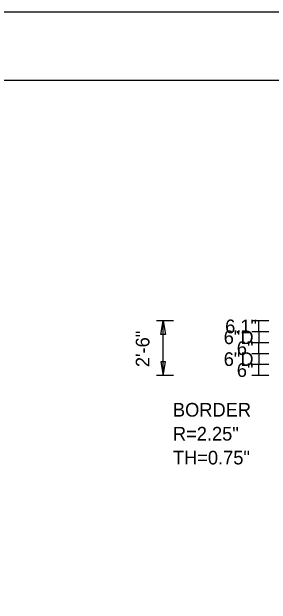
# Model space of a CAD drawing. Extents: x 1806251 to 1809821, y 414895 to 422886.
# Drawn here: x 1809675.736 to 1809677.16, y 415070.976 to 415074.226 of the extents above; entities that cross this region are included whole.
import ezdxf

# ---------------------------------------------------------------- set-up
doc = ezdxf.new("R2010")
doc.units = 0
doc.layers.add('GSDIMS', color=7, linetype='Continuous')
doc.layers.add('GSSHT', color=7, linetype='Continuous')

msp = doc.modelspace()

# ---------------------------------------------------------------- linework, layer by layer
at = {"layer": 'GSDIMS'}
for p, q in [((1809676.6233, 415072.5311), (1809676.5296, 415072.5311)), ((1809676.5671, 415072.2301), (1809676.5671, 415072.5311)), ((1809677.1483, 415072.5311), (1809677.0546, 415072.5311)), ((1809677.0921, 415072.4703), (1809677.0921, 415072.5311)), ((1809677.1483, 415072.4703), (1809677.0546, 415072.4703)), ((1809677.1483, 415072.4703), (1809677.0546, 415072.4703)), ((1809677.0921, 415072.4703), (1809677.0921, 415072.4103)), ((1809677.1483, 415072.4103), (1809677.0546, 415072.4103)), ((1809677.1483, 415072.4103), (1809677.0546, 415072.4103)), ((1809677.0921, 415072.3503), (1809677.0921, 415072.4103)), ((1809677.1483, 415072.3503), (1809677.0546, 415072.3503)), ((1809677.1483, 415072.3503), (1809677.0546, 415072.3503)), ((1809677.0921, 415072.3503), (1809677.0921, 415072.2903)), ((1809677.1483, 415072.2903), (1809677.0546, 415072.2903)), ((1809677.1483, 415072.2903), (1809677.0546, 415072.2903)), ((1809677.0921, 415072.2301), (1809677.0921, 415072.2903)), ((1809676.6233, 415072.2301), (1809676.5296, 415072.2301)), ((1809677.1483, 415072.2301), (1809677.0546, 415072.2301))]:
    msp.add_line(p, q, dxfattribs=at)
for points in [[(1809676.5671, 415072.5311), (1809676.5796, 415072.4561), (1809676.5546, 415072.4561)], [(1809676.5671, 415072.2301), (1809676.5796, 415072.3051), (1809676.5546, 415072.3051)]]:
    msp.add_lwpolyline(points, close=True, dxfattribs=at)
at = {"layer": 'GSSHT'}
msp.add_line((1809672.1349, 415074.2262), (1809684.8891, 415074.2262), dxfattribs=at)
msp.add_lwpolyline([(1809672.634, 415073.8512), (1809684.6381, 415073.8512), (1809684.6381, 415066.3475), (1809672.634, 415066.3475)], close=True, dxfattribs=at)

# ---------------------------------------------------------------- texts
at = {"layer": 'GSDIMS'}
for s, p in [('6.1"', (1809676.9076, 415072.4628)), ('6"D', (1809676.8996, 415072.4031)), ('6"', (1809676.9716, 415072.3431)), ('6"D', (1809676.8996, 415072.2831)), ('6"', (1809676.9716, 415072.2228)), ('BORDER', (1809676.6206, 415072.0051)), ('R=2.25"', (1809676.6206, 415071.8738)), ('TH=0.75"', (1809676.6206, 415071.7426))]:
    msp.add_text(s, height=0.075, dxfattribs=at).set_placement(p)
msp.add_text('2\'-6"', height=0.075, rotation=90, dxfattribs=at).set_placement((1809676.4916, 415072.2766))

doc.saveas('drawing.dxf')
